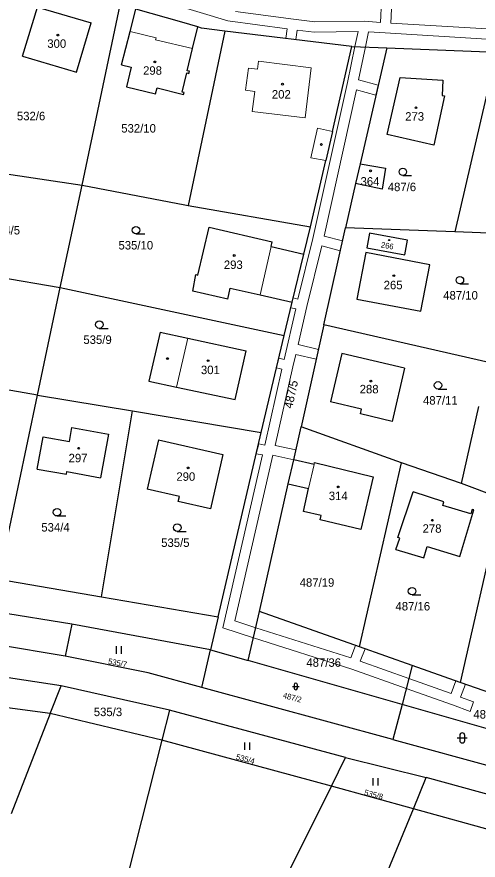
# Model space of a CAD drawing. Extents: x -701211 to -698780, y -1014269 to -1012378.
# Drawn here: x -700199.9 to -700107.3, y -1013298 to -1013128.7 of the extents above; entities that cross this region are included whole.
import ezdxf
from ezdxf.enums import TextEntityAlignment as Align

# ---------------------------------------------------------------- set-up
doc = ezdxf.new("R2010")
doc.units = 0
doc.header["$LTSCALE"] = 0.68
for name, color, linetype, lineweight in [('1', 7, 'Continuous', 25), ('13', 7, 'Continuous', 13), ('3', 7, 'Continuous', 25), ('4', 7, 'Continuous', 13), ('5', 7, 'Continuous', 25)]:
    doc.layers.add(name, color=color, linetype=linetype, lineweight=lineweight)
doc.layers.add('2', color=7, linetype='Continuous')

msp = doc.modelspace()

# ---------------------------------------------------------------- linework, layer by layer
at = {"layer": '1'}
for p, q in [((-700198.72, -1013136.58), (-700195.76, -1013126.7)), ((-700195.76, -1013126.7), (-700184.95, -1013129.9)), ((-700186.8, -1013162.44), (-700179.14, -1013126.24)), ((-700177.16, -1013131.64), (-700176.01, -1013127.12)), ((-700166.76, -1013129.73), (-700176.01, -1013127.12)), ((-700187.91, -1013139.78), (-700184.95, -1013129.9)), ((-700163.59, -1013130.71), (-700166.76, -1013129.73)), ((-700178.85, -1013138.29), (-700177.16, -1013131.64)), ((-700158.17, -1013131.52), (-700165.49, -1013166.54)), ((-700164.63, -1013135.06), (-700163.59, -1013130.71)), ((-700162.8, -1013130.95), (-700163.59, -1013130.71)), ((-700158.17, -1013131.52), (-700162.8, -1013130.95)), ((-700132.65, -1013134.61), (-700158.17, -1013131.52)), ((-700165.68, -1013139.49), (-700164.63, -1013135.06)), ((-700136.54, -1013151.71), (-700132.65, -1013134.61)), ((-700132.65, -1013134.61), (-700125.62, -1013134.88)), ((-700125.62, -1013134.88), (-700130.98, -1013158.18)), ((-700125.62, -1013134.88), (-700103.63, -1013135.74)), ((-700198.72, -1013136.58), (-700187.91, -1013139.78)), ((-700103.63, -1013135.74), (-700111.97, -1013171.82)), ((-700178.85, -1013138.29), (-700176.91, -1013138.76)), ((-700176.91, -1013138.76), (-700177.87, -1013142.72)), ((-700166.7, -1013143.79), (-700165.79, -1013139.93)), ((-700165.79, -1013139.93), (-700165.35, -1013140.04)), ((-700165.24, -1013139.59), (-700165.68, -1013139.49)), ((-700165.35, -1013140.04), (-700165.24, -1013139.59)), ((-700125.56, -1013152.27), (-700122.92, -1013140.83)), ((-700122.92, -1013140.83), (-700114.36, -1013141.4)), ((-700114.36, -1013141.4), (-700114.54, -1013144.45)), ((-700177.87, -1013142.72), (-700172.04, -1013144.13)), ((-700172.04, -1013144.13), (-700171.75, -1013142.95)), ((-700171.75, -1013142.95), (-700166.41, -1013144.25)), ((-700166.32, -1013143.88), (-700166.7, -1013143.79)), ((-700166.41, -1013144.25), (-700166.32, -1013143.88)), ((-700114.05, -1013144.53), (-700116.22, -1013154.4)), ((-700114.54, -1013144.45), (-700114.05, -1013144.53)), ((-700136.54, -1013151.71), (-700137.89, -1013157.52)), ((-700116.22, -1013154.4), (-700125.56, -1013152.27)), ((-700140.96, -1013170.81), (-700137.89, -1013157.52)), ((-700130.98, -1013158.18), (-700131.89, -1013162.14)), ((-700207.57, -1013159.32), (-700186.8, -1013162.44)), ((-700131.89, -1013162.14), (-700133.94, -1013171.05)), ((-700191.16, -1013183), (-700186.8, -1013162.44)), ((-700186.8, -1013162.44), (-700166.19, -1013166.42)), ((-700166.19, -1013166.42), (-700165.49, -1013166.54)), ((-700165.49, -1013166.54), (-700140.96, -1013170.81)), ((-700163.54, -1013180.52), (-700161.27, -1013170.86)), ((-700161.27, -1013170.86), (-700148.64, -1013173.86)), ((-700142.3, -1013176.33), (-700140.96, -1013170.81)), ((-700138.27, -1013190.52), (-700133.94, -1013171.05)), ((-700111.97, -1013171.82), (-700133.94, -1013171.05)), ((-700129.11, -1013172.08), (-700129.66, -1013175.02)), ((-700121.47, -1013173.53), (-700129.11, -1013172.08)), ((-700099.4, -1013172.29), (-700111.97, -1013171.82)), ((-700148.85, -1013174.77), (-700148.64, -1013173.86)), ((-700122.02, -1013176.47), (-700121.47, -1013173.53)), ((-700148.85, -1013174.77), (-700142.3, -1013176.33)), ((-700129.66, -1013175.02), (-700122.02, -1013176.47)), ((-700144.64, -1013185.96), (-700142.3, -1013176.33)), ((-700129.85, -1013176), (-700131.66, -1013185.36)), ((-700117.02, -1013178.43), (-700129.85, -1013176)), ((-700220.36, -1013178.09), (-700191.16, -1013183)), ((-700118.79, -1013187.78), (-700117.02, -1013178.43)), ((-700164.54, -1013183.77), (-700163.99, -1013180.42)), ((-700163.99, -1013180.42), (-700163.54, -1013180.52)), ((-700195.73, -1013204.59), (-700191.16, -1013183)), ((-700191.16, -1013183), (-700146.26, -1013192.65)), ((-700157.56, -1013185.33), (-700164.54, -1013183.77)), ((-700157.56, -1013185.33), (-700157.08, -1013183.12)), ((-700157.08, -1013183.12), (-700151.08, -1013184.49)), ((-700151.08, -1013184.49), (-700144.64, -1013185.96)), ((-700131.66, -1013185.36), (-700118.79, -1013187.78)), ((-700146.26, -1013192.65), (-700144.64, -1013185.96)), ((-700138.27, -1013190.52), (-700142.83, -1013210.97)), ((-700105.18, -1013198.07), (-700138.27, -1013190.52)), ((-700171.12, -1013191.99), (-700173.38, -1013201.79)), ((-700171.12, -1013191.99), (-700165.57, -1013193.19)), ((-700150.82, -1013212.11), (-700146.26, -1013192.65)), ((-700165.57, -1013193.19), (-700153.88, -1013195.73)), ((-700156.08, -1013205.52), (-700153.88, -1013195.73)), ((-700134.67, -1013196.25), (-700136.96, -1013205.93)), ((-700122.07, -1013199.19), (-700134.67, -1013196.25)), ((-700122.07, -1013199.19), (-700124.57, -1013209.9)), ((-700195.73, -1013204.59), (-700214.23, -1013201.43)), ((-700173.38, -1013201.79), (-700167.82, -1013203.01)), ((-700167.82, -1013203.01), (-700156.08, -1013205.52)), ((-700203.56, -1013241.55), (-700195.73, -1013204.59)), ((-700195.73, -1013204.59), (-700176.69, -1013207.78)), ((-700130.68, -1013207.41), (-700136.96, -1013205.93)), ((-700182.87, -1013245.09), (-700176.69, -1013207.78)), ((-700176.69, -1013207.78), (-700150.82, -1013212.11)), ((-700130.91, -1013208.39), (-700130.68, -1013207.41)), ((-700110.62, -1013222.38), (-700107.16, -1013206.92)), ((-700124.57, -1013209.9), (-700130.91, -1013208.39)), ((-700189.35, -1013213.92), (-700188.84, -1013211.12)), ((-700188.84, -1013211.12), (-700181.48, -1013212.47)), ((-700144.32, -1013217.58), (-700142.83, -1013210.97)), ((-700122.69, -1013218.2), (-700142.83, -1013210.97)), ((-700195.84, -1013219.45), (-700194.62, -1013212.96)), ((-700194.62, -1013212.96), (-700189.35, -1013213.92)), ((-700181.48, -1013212.47), (-700183.08, -1013221.21)), ((-700159.47, -1013249.1), (-700150.82, -1013212.11)), ((-700171.46, -1013213.61), (-700173.7, -1013223.51)), ((-700171.46, -1013213.61), (-700158.57, -1013216.54)), ((-700158.57, -1013216.54), (-700161.03, -1013227.42)), ((-700145.42, -1013222.43), (-700144.32, -1013217.58)), ((-700140.22, -1013218.52), (-700144.32, -1013217.58)), ((-700195.84, -1013219.45), (-700189.95, -1013220.46)), ((-700140.22, -1013218.52), (-700140.14, -1013218.16)), ((-700140.14, -1013218.16), (-700128.36, -1013220.99)), ((-700131.12, -1013255.15), (-700122.69, -1013218.2)), ((-700110.62, -1013222.38), (-700122.69, -1013218.2)), ((-700189.95, -1013220.46), (-700189.86, -1013219.97)), ((-700189.86, -1013219.97), (-700183.08, -1013221.21)), ((-700128.36, -1013220.99), (-700130.87, -1013231.58)), ((-700151.2, -1013248.05), (-700145.42, -1013222.43)), ((-700145.42, -1013222.43), (-700141.33, -1013223.36)), ((-700102.54, -1013225.42), (-700110.62, -1013222.38)), ((-700167.26, -1013224.96), (-700173.7, -1013223.51)), ((-700142.38, -1013227.94), (-700141.33, -1013223.36)), ((-700123.42, -1013233.2), (-700120.37, -1013224)), ((-700114.19, -1013226.05), (-700120.37, -1013224)), ((-700167.48, -1013225.94), (-700167.26, -1013224.96)), ((-700161.03, -1013227.42), (-700167.48, -1013225.94)), ((-700114.41, -1013226.78), (-700114.19, -1013226.05)), ((-700102.54, -1013225.42), (-700110.94, -1013262.28)), ((-700138.84, -1013228.79), (-700142.38, -1013227.94)), ((-700108.78, -1013228.46), (-700114.41, -1013226.78)), ((-700110.98, -1013236.99), (-700108.18, -1013227.65)), ((-700108.51, -1013227.56), (-700108.78, -1013228.46)), ((-700108.18, -1013227.65), (-700108.51, -1013227.56)), ((-700139.03, -1013229.65), (-700138.84, -1013228.79)), ((-700130.87, -1013231.58), (-700139.03, -1013229.65)), ((-700123.8, -1013235.61), (-700123.05, -1013233.32)), ((-700123.05, -1013233.32), (-700123.42, -1013233.2)), ((-700118.21, -1013237.27), (-700117.52, -1013235)), ((-700117.52, -1013235), (-700110.98, -1013236.99)), ((-700123.8, -1013235.61), (-700118.21, -1013237.27)), ((-700203.56, -1013241.55), (-700182.87, -1013245.09)), ((-700188.84, -1013250.56), (-700230.54, -1013243.86)), ((-700182.87, -1013245.09), (-700159.47, -1013249.1)), ((-700153.43, -1013257.9), (-700151.2, -1013248.05)), ((-700131.12, -1013255.15), (-700151.2, -1013248.05)), ((-700159.47, -1013249.1), (-700161.02, -1013255.73)), ((-700188.84, -1013250.56), (-700190.18, -1013256.99)), ((-700161.02, -1013255.73), (-700188.84, -1013250.56)), ((-700190.18, -1013256.99), (-700216.33, -1013252.72)), ((-700120.54, -1013258.89), (-700131.12, -1013255.15)), ((-700173.5, -1013260.37), (-700190.18, -1013256.99)), ((-700162.79, -1013263.29), (-700161.02, -1013255.73)), ((-700161.02, -1013255.73), (-700153.43, -1013257.9)), ((-700191.02, -1013262.97), (-700220.78, -1013258.4)), ((-700122.58, -1013266.7), (-700153.43, -1013257.9)), ((-700162.79, -1013263.29), (-700173.5, -1013260.37)), ((-700120.54, -1013258.89), (-700122.58, -1013266.7)), ((-700110.94, -1013262.28), (-700120.54, -1013258.89)), ((-700193.17, -1013268.5), (-700191.02, -1013262.97)), ((-700169.22, -1013267.87), (-700191.02, -1013262.97)), ((-700124.41, -1013273.74), (-700162.79, -1013263.29)), ((-700104.53, -1013264.52), (-700110.94, -1013262.28)), ((-700193.17, -1013268.5), (-700214.6, -1013265.72)), ((-700122.58, -1013266.7), (-700124.41, -1013273.74)), ((-700064.92, -1013283.16), (-700122.58, -1013266.7)), ((-700193.17, -1013268.5), (-700201.01, -1013288.64)), ((-700170.76, -1013273.9), (-700193.17, -1013268.5)), ((-700169.22, -1013267.87), (-700170.76, -1013273.9)), ((-700133.94, -1013277.34), (-700169.22, -1013267.87)), ((-700170.76, -1013273.9), (-700177.62, -1013300.82)), ((-700136.72, -1013283.1), (-700170.76, -1013273.9)), ((-700124.41, -1013273.74), (-700057.06, -1013292.27)), ((-700136.72, -1013283.1), (-700133.94, -1013277.34)), ((-700133.94, -1013277.34), (-700117.73, -1013281.39)), ((-700120.3, -1013287.65), (-700117.73, -1013281.39)), ((-700096.6, -1013287.2), (-700117.73, -1013281.39)), ((-700164.04, -1013337.79), (-700136.72, -1013283.1)), ((-700120.3, -1013287.65), (-700136.72, -1013283.1)), ((-700129.01, -1013308.85), (-700120.3, -1013287.65)), ((-700096.87, -1013294.15), (-700120.3, -1013287.65))]:
    msp.add_line(p, q, dxfattribs=at)
msp.add_lwpolyline([(-700130.98, -1013158.18), (-700125.89, -1013159.08), (-700126.57, -1013163.27), (-700131.89, -1013162.14)], dxfattribs=at)
at = {"layer": '13'}
for points in [[(-700168.67, -1013126.14), (-700157.52, -1013129.47), (-700145.64, -1013131.06), (-700145.89, -1013133.01), (-700143.87, -1013133.25), (-700143.63, -1013131.32), (-700140.18, -1013131.75), (-700131.4, -1013131.61), (-700132.03, -1013134.63), (-700133.52, -1013141.82), (-700140.45, -1013173.18), (-700143.46, -1013185.34), (-700144.43, -1013185.1), (-700144.64, -1013185.96), (-700144.91, -1013187.07), (-700143.92, -1013187.32), (-700146.23, -1013197.43), (-700147.32, -1013197.16), (-700147.78, -1013199.14), (-700146.69, -1013199.4), (-700150.14, -1013214.64), (-700151.35, -1013214.39), (-700151.82, -1013216.37), (-700150.59, -1013216.62), (-700158.57, -1013251.33), (-700152.39, -1013253.31), (-700132.62, -1013259.62), (-700121.74, -1013263.49), (-700112.48, -1013266.79), (-700108.91, -1013268.1), (-700108.2, -1013266.17), (-700110.82, -1013265.21), (-700109.87, -1013262.65), (-700110.94, -1013262.28)], [(-700126.69, -1013125.5), (-700126.87, -1013129.78), (-700130.1, -1013129.53), (-700140.07, -1013129.69), (-700144.38, -1013129.15), (-700156.02, -1013127.59)], [(-700090.79, -1013126.99), (-700090.96, -1013131.49), (-700105.47, -1013131.07), (-700124.84, -1013129.92), (-700124.65, -1013125.59)], [(-700110.94, -1013262.28), (-700111.78, -1013261.98), (-700112.73, -1013264.52), (-700121.22, -1013261.49), (-700130.95, -1013258.02), (-700129.98, -1013255.55), (-700131.12, -1013255.15), (-700131.9, -1013254.88), (-700132.88, -1013257.37), (-700151.93, -1013251.29), (-700156.14, -1013249.95), (-700148.49, -1013216.67), (-700144.32, -1013217.58), (-700143.88, -1013215.62), (-700148.04, -1013214.69), (-700144.47, -1013198.9), (-700143.86, -1013196.45), (-700139.81, -1013197.41), (-700139.36, -1013195.42), (-700143.39, -1013194.47), (-700141.7, -1013186.81), (-700138.69, -1013174.66), (-700134.96, -1013175.65), (-700134.52, -1013173.66), (-700138.23, -1013172.68), (-700131.74, -1013143.31), (-700127.81, -1013144.4), (-700127.35, -1013142.41), (-700131.31, -1013141.32), (-700129.94, -1013134.71), (-700129.31, -1013131.65), (-700125.97, -1013131.91), (-700105.56, -1013133.13)]]:
    msp.add_lwpolyline(points, dxfattribs=at)
at = {"layer": '3'}
for p, q in [((-700122.413, -1013160.54), (-700120.663, -1013160.54)), ((-700175.973, -1013172.25), (-700174.223, -1013172.25)), ((-700110.963, -1013182.29), (-700109.213, -1013182.29)), ((-700183.333, -1013191.21), (-700181.583, -1013191.21)), ((-700115.353, -1013203.39), (-700113.603, -1013203.39)), ((-700191.813, -1013228.87), (-700190.063, -1013228.87)), ((-700167.683, -1013231.96), (-700165.933, -1013231.96)), ((-700120.563, -1013244.71), (-700118.813, -1013244.71)), ((-700179.871, -1013256.52), (-700179.871, -1013255.02)), ((-700178.87, -1013256.52), (-700178.87, -1013255.02)), ((-700144.591, -1013263.071), (-700143.249, -1013263.071)), ((-700144.255, -1013262.735), (-700144.255, -1013263.406)), ((-700143.585, -1013263.406), (-700143.585, -1013262.735)), ((-700111.491, -1013273.421), (-700109.489, -1013273.421)), ((-700110.991, -1013272.921), (-700110.991, -1013273.922)), ((-700109.989, -1013273.922), (-700109.989, -1013272.921)), ((-700154.121, -1013275.84), (-700154.121, -1013274.34)), ((-700153.12, -1013275.84), (-700153.12, -1013274.34)), ((-700128.371, -1013282.98), (-700128.371, -1013281.48)), ((-700127.37, -1013282.98), (-700127.37, -1013281.48))]:
    msp.add_line(p, q, dxfattribs=at)
for centre in [(-700122.4129, -1013159.7898), (-700175.9729, -1013171.4998), (-700110.9629, -1013181.5398), (-700183.3329, -1013190.4598), (-700115.3529, -1013202.6398), (-700191.8129, -1013228.1198), (-700167.6829, -1013231.2098), (-700120.5629, -1013243.9598)]:
    msp.add_circle(centre, 0.75, dxfattribs=at)
for centre, radius, start, end in [((-700143.92, -1013262.7356), 0.335, 0, 180), ((-700143.92, -1013263.4056), 0.335, 180, 359.98789), ((-700110.49, -1013272.9209), 0.5, 0, 180), ((-700110.49, -1013273.9209), 0.5, 180, 359.98789)]:
    msp.add_arc(centre, radius, start, end, dxfattribs=at)
at = {"layer": '4'}
for p, q in [((-700171.95, -1013132.86), (-700177.16, -1013131.64)), ((-700172.03, -1013133.3), (-700171.95, -1013132.86)), ((-700164.63, -1013135.06), (-700172.03, -1013133.3)), ((-700151.38, -1013137.59), (-700151.58, -1013139.18)), ((-700140.79, -1013138.94), (-700151.38, -1013137.59)), ((-700153.98, -1013143.41), (-700153.41, -1013138.95)), ((-700153.41, -1013138.95), (-700151.58, -1013139.18)), ((-700142.03, -1013148.96), (-700140.79, -1013138.94)), ((-700152.65, -1013147.7), (-700142.03, -1013148.96)), ((-700140.88, -1013156.97), (-700139.52, -1013151.04)), ((-700139.52, -1013151.04), (-700136.54, -1013151.71)), ((-700137.89, -1013157.52), (-700140.88, -1013156.97)), ((-700151.08, -1013184.49), (-700148.85, -1013174.77)), ((-700165.57, -1013193.19), (-700167.82, -1013203.01)), ((-700141.33, -1013223.36), (-700140.22, -1013218.52))]:
    msp.add_line(p, q, dxfattribs=at)
msp.add_lwpolyline([(-700153.98, -1013143.41), (-700152.14, -1013143.64), (-700152.65, -1013147.7)], dxfattribs=at)
at = {"layer": '5'}
for centre, radius in [((-700191.6368, -1013132.3392), 0.175), ((-700172.1968, -1013137.7192), 0.175), ((-700146.5668, -1013142.1892), 0.175), ((-700119.7768, -1013146.9192), 0.175), ((-700138.7668, -1013154.2992), 0.175), ((-700128.8968, -1013159.5792), 0.175), ((-700125.1446, -1013173.4794), 0.1172), ((-700156.2468, -1013176.5792), 0.175), ((-700124.2268, -1013180.6292), 0.175), ((-700169.6468, -1013197.2792), 0.175), ((-700161.5068, -1013197.6892), 0.175), ((-700128.8268, -1013201.7892), 0.175), ((-700187.4768, -1013215.2792), 0.175), ((-700165.5068, -1013219.2192), 0.175), ((-700135.3768, -1013223.0392), 0.175), ((-700116.4868, -1013229.7292), 0.175)]:
    msp.add_circle(centre, radius, dxfattribs=at)

# ---------------------------------------------------------------- texts
at = {"layer": '2'}
for s, p in [('300', (-700193.77, -1013134.895)), ('298', (-700174.55, -1013140.295)), ('202', (-700148.7, -1013145.075)), ('532/6', (-700199.87, -1013149.435)), ('273', (-700121.94, -1013149.515)), ('532/10', (-700178.93, -1013151.905)), ('487/6', (-700125.44, -1013163.665)), ('534/5', (-700204.93, -1013172.355)), ('535/10', (-700179.49, -1013175.375)), ('293', (-700158.34, -1013179.285)), ('265', (-700126.26, -1013183.355)), ('487/10', (-700114.31, -1013185.415)), ('535/9', (-700186.53, -1013194.335)), ('301', (-700162.94, -1013200.395)), ('288', (-700131.08, -1013204.255)), ('487/11', (-700118.37, -1013206.515)), ('297', (-700189.5, -1013218.085)), ('290', (-700167.87, -1013221.805)), ('314', (-700137.28, -1013225.685)), ('534/4', (-700194.97, -1013231.995)), ('278', (-700118.45, -1013232.235)), ('535/5', (-700170.92, -1013235.085)), ('487/19', (-700143.12, -1013243.075)), ('487/16', (-700123.89, -1013247.835))]:
    msp.add_text(s, height=1.7, dxfattribs=at).set_placement(p)
for s, p in [('364', (-700129.009, -1013162.555)), ('487/36', (-700138.3, -1013259.145)), ('535/3', (-700181.6, -1013269.045)), ('487/15', (-700104.78, -1013269.535))]:
    msp.add_text(s, height=1.7, dxfattribs=at).set_placement(p, align=Align.CENTER)
for s, rotation, p in [('266', 350, (-700125.619, -1013175.1691)), ('535/7', 349, (-700179.7688, -1013258.9096)), ('487/2', 345, (-700144.7475, -1013265.8554)), ('535/4', 345, (-700154.1575, -1013278.2054)), ('535/8', 345, (-700128.4075, -1013285.3454))]:
    msp.add_text(s, height=1.14, rotation=rotation, dxfattribs=at).set_placement(p, align=Align.CENTER)
msp.add_text('487/5', height=1.7, rotation=78, dxfattribs=at).set_placement((-700144.614, -1013207.398))

doc.saveas('drawing.dxf')
